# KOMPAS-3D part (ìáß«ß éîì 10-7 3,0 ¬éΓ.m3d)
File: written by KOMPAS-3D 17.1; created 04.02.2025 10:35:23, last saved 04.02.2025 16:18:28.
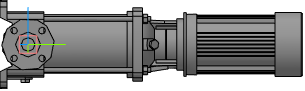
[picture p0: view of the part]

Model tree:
1. Операция без истории:1  (labels: Насос ВМН 10-7 3,0 кВт)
